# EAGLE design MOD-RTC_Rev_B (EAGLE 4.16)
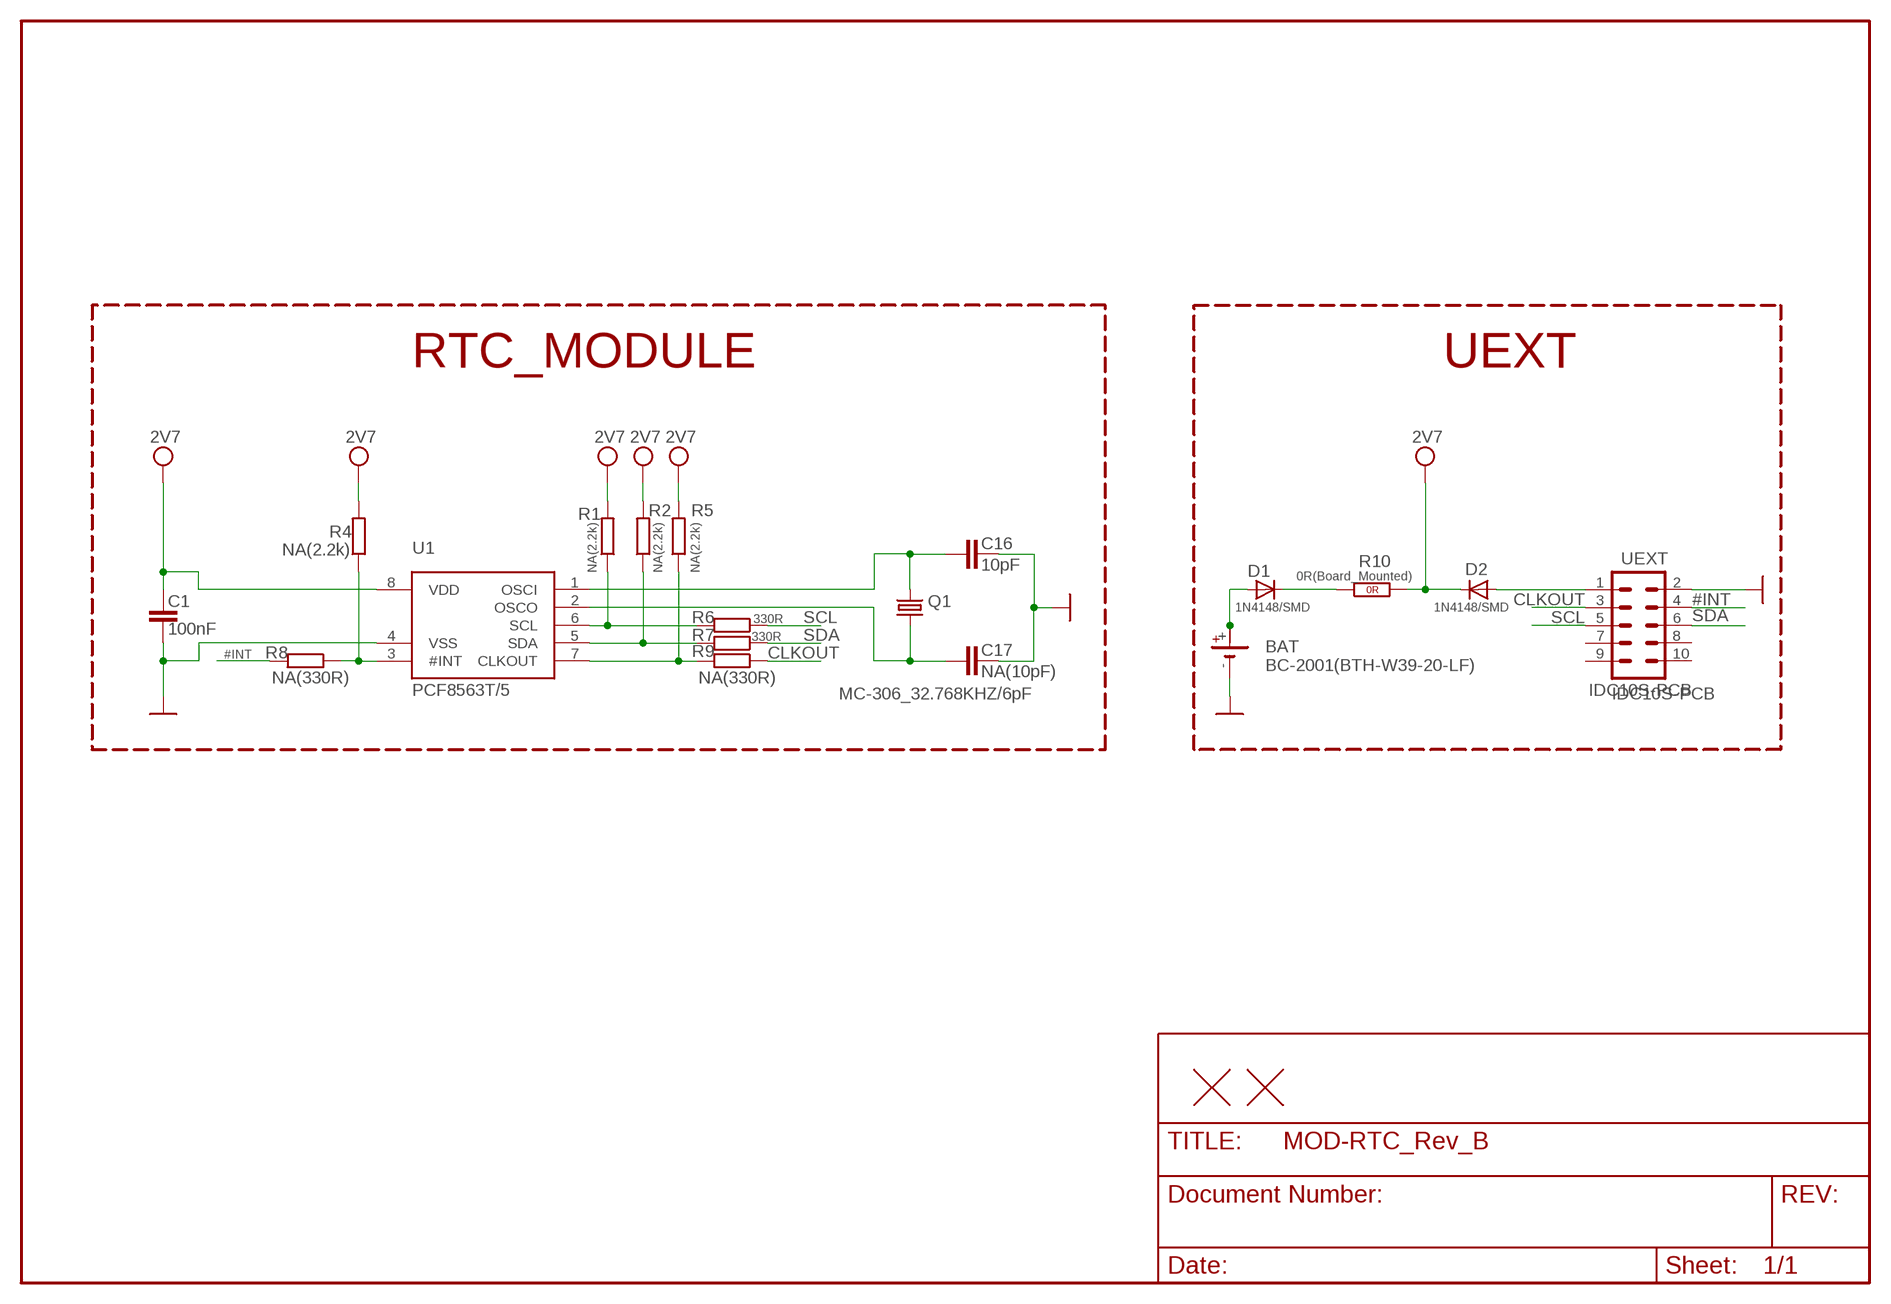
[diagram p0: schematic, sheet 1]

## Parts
BAT  BC-2001(BTH-W39-20-LF)  BFLATWISE  [BAT-FLATWISE]
C1  100nF  C-EUC0603_5MIL  [C0603_5MIL]
C16  10pF  C-EUC0603_5MIL  [C0603_5MIL]
C17  NA(10pF)  C-EUC0603_5MIL  [C0603_5MIL]
D1  1N4148/SMD  D-MLL-34  [MELF-MLL34]
D2  1N4148/SMD  D-MLL-34  [MELF-MLL34]
Q1  MC-306_32.768KHZ/6pF  MC-306_32.768KHZ/SMD_8038  [MC-306]
R1  NA(2.2k)  R-EU_R0603_5MIL  [R0603_5MIL]
R2  NA(2.2k)  R-EU_R0603_5MIL  [R0603_5MIL]
R4  NA(2.2k)  R-EU_R0603_5MIL  [R0603_5MIL]
R5  NA(2.2k)  R-EU_R0603_5MIL  [R0603_5MIL]
R6  330R  R-EU_R0603_5MIL  [R0603_5MIL]
R7  330R  R-EU_R0603_5MIL  [R0603_5MIL]
R8  NA(330R)  R-EU_R0603_5MIL  [R0603_5MIL]
R9  NA(330R)  R-EU_R0603_5MIL  [R0603_5MIL]
R10  0R(Board_Mounted)  R_0R0R(NA)  [0603_0R]
U1  PCF8563T/5  PCF8563  [SO-8]
U$5  FIDUCIAL1X2  [FIDUCIAL-1X2]
U$6  FIDUCIAL1X2  [FIDUCIAL-1X2]
UEXT  IDC10S-PCB  ML10SMD_1  [ML10L_PADS_FEMAIL]

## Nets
#INT: R8.2 UEXT.4
CLKOUT: R9.1 UEXT.3
GND: BAT.- C1.1 C16.2 C17.2 U1.4(VSS) UEXT.2
N$1 [bat]: BAT.+ BAT.+@1(+) D1.2(A)
N$2: D2.2(A) UEXT.1
N$3: D1.1(C) R10.1(1.1)
N$4: R4.1 R8.1 U1.3(#INT)
N$6: R1.1 R6.2 U1.6(SCL)
N$7: R2.1 R7.2 U1.5(SDA)
N$9: R5.1 R9.2 U1.7(CLKOUT)
N$43: C17.1 Q1.4 U1.2(OSCO)
N$44: C16.1 Q1.1 U1.1(OSCI)
SCL: R6.1 UEXT.5
SDA: R7.1 UEXT.6
VCC: C1.2 D2.1(C) R1.2 R2.2 R4.2 R5.2 R10.2(1.2) U1.8(VDD) ; supply symbol labelled 2V7
Unconnected: UEXT.7 UEXT.8 UEXT.9 UEXT.10

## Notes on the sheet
- RTC_MODULE | UEXT
- IDC10S-PCB

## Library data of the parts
BAT = DOUBLE-SIDE:B: LI BATTERY Varta
C1 C16 C17 = rcl:C-EU: CAPACITOR, European symbol
D1 D2 = semicon-smd-ipc:D-: DIODE
Q1 = crystal:MC-306
R1 R2 R4-R9 = rcl:R-EU_: RESISTOR, European symbol
R10 = OLIMEX_DISCRET:R_0R
U1 = OLIMEX_IC:PCF8563: Real-time clock/calendar
U$5 U$6 = SparkFunEagle-6-6-07:FIDUCIAL: Fiducial Alignment Points
UEXT = con-harting-ml:ML10: HARTING

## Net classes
1 bat: drill 0.254 mm

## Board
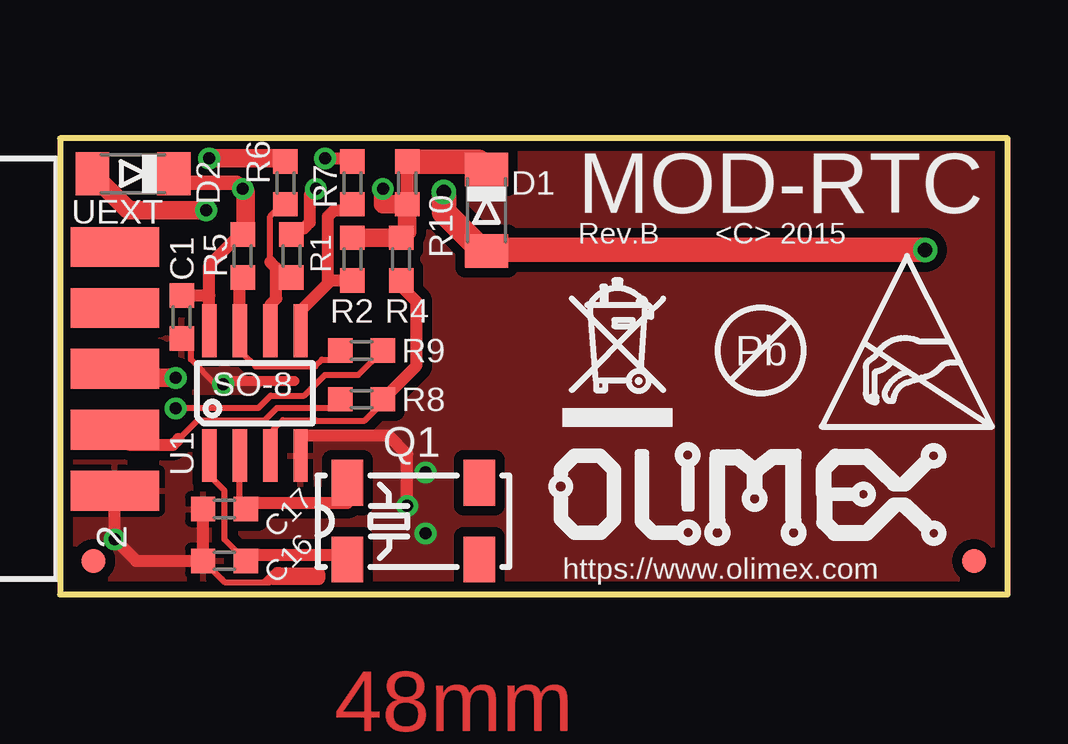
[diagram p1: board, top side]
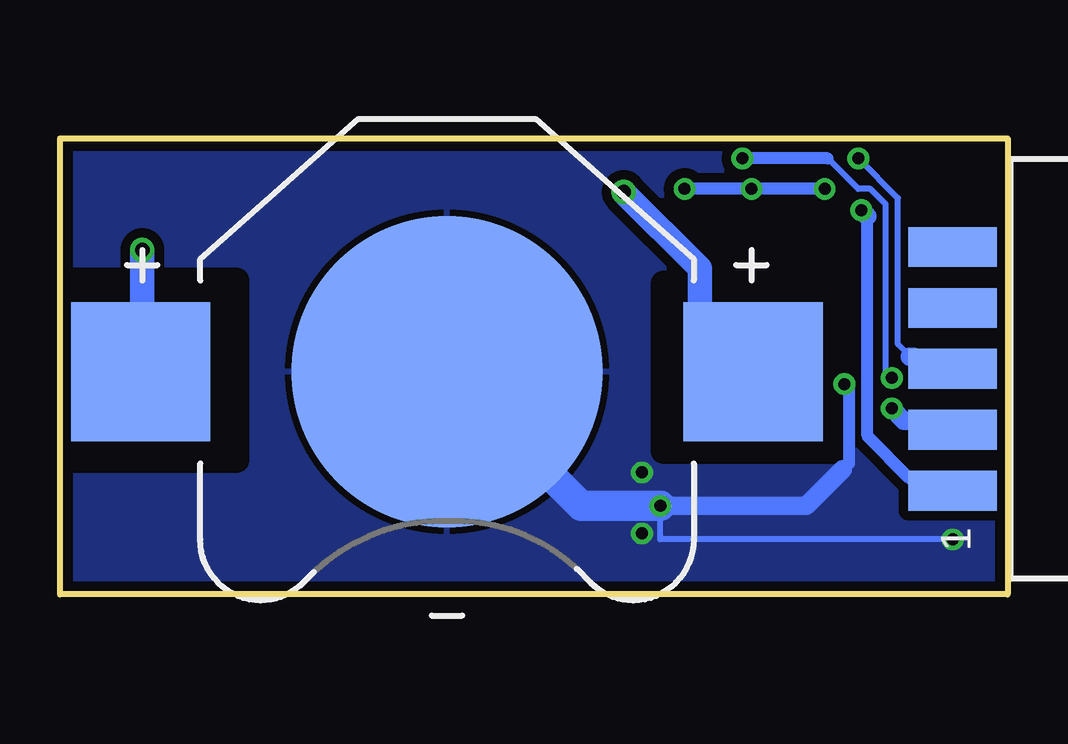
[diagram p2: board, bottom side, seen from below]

Size 39.5 x 19 mm. Coordinates in mm from the lower left corner, seen from the top.
Outline: 0,0 39.5,0 39.5,19 0,19 0,0
Copper layers (1+16): Top 0.035mm / dielectric 1.5mm / Bottom 0.035mm
Design rules "default": minimum track width 10mil, minimum drill 0.4mm, track to track 9.5mil, track to pad 9.5mil, pad to pad 9.5mil, via to via 9.5mil, smd to smd 1mil, copper to edge 10mil, drill to drill 8mil, minimum pad ring 10mil, minimum via ring 8mil, stop-mask expansion 4mil, vias tented up to drill 32mil, thermal gap 10mil
bRestrict: area 7,6 to 14.4,13; area 32.1,5.6 to 39.1,13.1

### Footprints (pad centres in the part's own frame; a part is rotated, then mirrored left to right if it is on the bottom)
BAT-FLATWISE = smd 5.8 x 5.8: + 12.764,0; +@1 -12.764,0 | smd 13 x 13: - 0,0
C0603_5MIL = smd 1.016 x 1.016: 1 -0.889,0; 2 0.889,0
MELF-MLL34 = smd 1.4 x 1.8: 1 -1.7,0; 2 1.7,0
MC-306 = smd 1.3 x 1.9: 1 -2.75,-1.6; 2 2.75,-1.6; 3 2.75,1.6; 4 -2.75,1.6
R0603_5MIL = smd 1.016 x 1.016: 1 -0.889,0; 2 0.889,0
0603_0R = smd 1.016 x 1.016: 1 -0.889,0; 2 0.889,0
SO-8 = smd 0.6 x 2.2: 1 -1.905,-2.6; 2 -0.635,-2.6; 3 0.635,-2.6; 4 1.905,-2.6; 5 1.905,2.6; 6 0.635,2.6; 7 -0.635,2.6; 8 -1.905,2.6
FIDUCIAL-1X2 = smd 1 x 1: 1 0,0
ML10L_PADS_FEMAIL = smd 1.651 x 3.683 bottom: 1 -5.08,-3.429; 3 -2.54,-3.429; 5 0,-3.429; 7 2.54,-3.429; 9 5.08,-3.429 | smd 1.651 x 3.683: 2 -5.08,-3.429; 4 -2.54,-3.429; 6 0,-3.429; 8 2.54,-3.429; 10 5.08,-3.429

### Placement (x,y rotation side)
BAT  23.37,9.27 0 bottom
C1  5.08,11.56 90 top
C16  6.86,1.4 180 top
C17  6.86,3.56 180 top
D1  17.78,16 270 top
D2  3.05,17.53 180 top
Q1  14.73,3.05 0 top
R1  9.65,14.1 90 top
R2  12.19,13.97 90 top
R4  14.22,13.97 90 top
R5  7.62,14.1 90 top
R6  9.4,17.14 270 top
R7  12.19,17.14 270 top
R8  12.57,8.13 180 top
R9  12.57,10.16 180 top
R10  14.48,17.14 270 top
U1  8.13,8.38 0 top
U$1  [RECYCLE_BIN1/8]  20.95,6.99 0 top
U$2  [PB_SMALL]  29.21,10.16 0 top
U$3  [OLIMEX1_V]  38.1,1.91 0 top
U$4  [ESD_SYMBOL]  31.75,6.99 0 top
U$5  1.4,1.4 0 top
U$6  38.1,1.4 0 top
UEXT  -1.14,9.4 90 top

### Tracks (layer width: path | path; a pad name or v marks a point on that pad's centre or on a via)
#INT
  Top 0.254: 11.56,8 11.33,7.77 9.04,7.77 8.53,7.26 5.74,7.26 4.94,6.46
  Top 0.508: 11.56,8 R8.2 | UEXT.4 2.92,6.22 4.7,6.22 4.94,6.46
CLKOUT  (via drill 0.5)
  Top 0.254: v4.83,7.75 4.85,7.77 8.28,7.77 8.79,8.28 10.19,8.28 11.05,9.14 12.45,9.14 R9.1
  Bottom 0.762: UEXT.3 2.67,7.24 4.32,7.24 v4.83,7.75
GND  (via drill 0.5)
  Top 0.254: C1.1 5.46,10.29 5.46,9.78 6.48,8.76 6.73,8.76 v6.81,8.76 | C16.2 6.86,0.51 8.51,0.51 | 8.51,0.51 8.89,0.89 9.07,0.89 | 8.51,0.51 8.76,0.51 9.14,0.89
  Top 0.406: 6.73,8.76 6.73,8.89 9.78,8.89
  Top 0.508: C17.2 C16.2 3.17,1.4 v2.29,2.29 UEXT.2 | U1.4 10.03,6.6 13.72,6.6 14.48,5.84 v14.48,3.68 | 9.07,0.89 9.14,0.89 10.79,0.89 10.79,0.64 8.89,0.64
  Bottom 0.254: v2.29,2.29 14.48,2.29 v14.48,3.68
  Bottom 0.508: 6.86,5.21 6.6,5.46 6.6,8.56 v6.81,8.76
  Bottom 0.762: v14.48,3.68 8.38,3.68 6.86,5.21
  Bottom 1.27: v14.48,3.68 17.78,3.68 BAT.-
  other vias: 15.24,5.08 15.24,2.54
  pour Top (isolate 0.406, rank 2): 43.05,20.7 -5.59,20.7 -5.59,-1.4 43.05,-1.4
  pour Bottom (isolate 0.406, rank 2): 45.97,22.73 -8.76,22.73 -8.76,-3.43 45.97,-3.43
N$1  (via drill 0.6)
  Top 1.016: v16,16.76 16,15.92 17.7,14.22 D1.2 17.86,14.3 17.91,14.35 v36.07,14.35
  Bottom 1.016: BAT.+ 12.83,11.49 12.83,13.59 v16,16.76 | v36.07,14.35 36.07,9.34 BAT.+@1
N$2  (via drill 0.5)
  Top 0.762: D2.2 2.87,16 v6.1,16
  Bottom 0.508: UEXT.1 2.79,4.83 4.06,4.83 5.84,6.6 5.84,15.75
  Bottom 0.762: 5.84,15.75 v6.1,16
N$3
  Top 1.016: R10.1 17.45,18.03 D1.1
N$4
  Top 0.254: U1.3 8.89,5.91 8.89,6.86 9.3,7.26 10.64,7.26 10.67,7.24 12.7,7.24 13.46,8 R8.1
  Top 0.508: R4.1 14.22,12.83 14.86,12.19 14.86,9.53 R8.1
N$6
  Top 0.254: R6.2 9.27,16.26 8.76,15.75 8.76,13.84
  Top 0.508: U1.6 8.76,12.06 9.02,12.32 9.02,13.21 | 9.02,13.21 R1.1 | 9.02,13.21 9.02,13.59 8.76,13.84
N$7
  Top 0.508: U1.5 10.03,11.81 11.18,12.95 11.18,13.08 | 11.18,13.08 R2.1 | R7.2 11.94,16 11.43,16 11.18,15.75 11.18,13.08
N$9
  Top 0.254: R9.2 11.68,9.78 10.92,9.78 10.64,9.5 8.15,9.5 7.62,10.03 7.62,10.86 U1.7
  Top 0.508: U1.7 7.49,13.08 R5.1
N$43
  Top 0.254: U1.2 7.49,3.81 C17.1
  Top 0.508: C17.1 7.75,3.81 11.98,3.81 Q1.4
N$44
  Top 0.254: U1.1 6.22,4.95 6.86,4.32 6.86,2.29 C16.1
  Top 0.508: Q1.1 11.98,1.65 7.75,1.65 C16.1
SCL  (via drill 0.5)
  Top 0.762: v6.22,18.16 9.53,18.16 R6.1
  Bottom 0.254: 4.06,9.91 4.57,10.41 4.57,16.51 v6.22,18.16
  Bottom 0.762: UEXT.5 3.17,9.4 3.56,9.78 3.81,9.78 3.94,9.91 4.06,9.91
SDA  (via drill 0.5)
  Top 0.508: R7.1 12.06,18.16 v11.05,18.16
  Top 0.762: UEXT.6 2.41,9.4 2.79,9.02 v4.83,9.02
  Bottom 0.254: v4.83,9.02 5.08,9.27 5.08,16.26 5.71,16.89 6.22,16.89 7.49,18.16
  Bottom 0.508: 7.49,18.16 v11.05,18.16
VCC  (via drill 0.5)
  Top 0.508: U1.8 6.22,12.45 | R5.2 7.49,14.99 6.22,13.72 6.22,12.45 | 6.22,12.45 C1.2 | R1.2 9.91,15.24 10.16,15.24 10.41,15.49 10.41,16.64 v10.67,16.89
  Top 0.61: D2.1 5.13,17.14 7.37,17.14 v7.62,16.89
  Top 0.762: R2.2 R4.2 14.48,15.11 R10.2 13.46,16.26 v13.46,16.89 | R5.2 7.75,15.11 7.75,16.76 v7.62,16.89
  Bottom 0.508: v7.62,16.89 v10.67,16.89 v13.46,16.89

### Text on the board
Top: 48mm | Bez bial pechat na bottom | Da se premesti 2-kata na UEXT po-blizo da kraka i po-dale4e ot fiduciala!
tNames: MOD-RTC | Rev.B | <C> 2015 | https://www.olimex.com
bStop: MOD-RTC | Rev.B | 1 | OLIMEX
